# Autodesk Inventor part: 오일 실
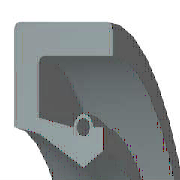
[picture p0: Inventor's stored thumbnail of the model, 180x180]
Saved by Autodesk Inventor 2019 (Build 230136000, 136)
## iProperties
IsCustomPart: 0
Created: 2016-05
Part Number: 오일 실
Material: 고무
Description: 오일-실
Document SubType Name: Modeling
Standard: KS B 2804
Designer: mduedu
Standards Organization: KS
Language: ko-KR
Size Designation: S - 17 30 8
Categories: <MemberInstance><Categories><Category DisplayName="샤프트 부품" InternalName="7f7aeb1f-a693-4053-b835-cee3144e0d98" Mnemonic="SHFT"><Category DisplayName="실링" Intern
Density: 0.93 g/cm^3
Appearance: 고무 - 검은색 - 버전 1.1
Author: mduedu
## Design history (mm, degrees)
revolve "본체" stored, may be unused: angle "d17" = 90 deg
revolve "스프링1" stored, may be unused: angle "d18" = 90 deg
body "Solid1"
sketch "스케치1"
  geometry: L1 (0, 15)-(8, 15); L2 (8, 15)-(8, 13.75); L3 (8, 13.75)-(1.75, 13.75); L4 (0, 15)-(0, 10.6); L5 (0, 10.6)-(1.75, 10.25); L6 (1.75, 10.25)-(4.9, 8.5); L7 (4.9, 8.5)-(0, 8.5); L8 (6.3, 9.375)-(6.3, 10.6); L9 (0, 0)-(9.586, 0) reference; L10 (4.9, 8.5)-(6.3, 9.375); L11 (0, 18)-(0, -3) reference; L12 (-1.917, 0)-(11.503, 0) reference; L13 (4.2, 10.6)-(1.75, 11.09); L14 (1.75, 11.09)-(1.75, 13.75); L15 (6.3, 10.6)-(5.6, 10.6); C1 r 0.455 at (4.9, 10.6); A1 r 0.7 centre (4.9, 10.6) between (5.6, 10.6) and (4.2, 10.6)
  constraints: 26 end point, 5 horizontal alignment, 4 perpendicular, 2 centre point, 2 collinear, 2 horizontal, 2 parallel, 2 point on circle, 2 point on line, 2 vertical alignment, 1 coincident
  dimensions: "d0" = 30 diameter of L1 L9 (= SD2); "d1" = 18.75 diameter of L8.start L9 (= ABDM); "d2" = 1.25 distance of L1.end L2.end (computed from SD); "d3" = 0.91 diameter of C1 (= SPDI); "d4" = 1.4 diameter of A1 (= SPDA); "d5" = 17 diameter of L6.end L9 (= NND); "d6" = 20.5 diameter of L5.end L9 (= TKDM); "d7" = 21.2 diameter of L4.end L9 (= HLDM); "d8" = 4.9 distance from line of C1.centre L4 (= SPDST); "d9" = 6.3 distance between parallel lines of L8 L4 (= SDI); "d10" = 8 distance between parallel lines of L2 L4 (= SWDT); "d12" = 1.75 distance between parallel lines of L14 L4 (= SD)
fillet "모깎기1" dims "d11" = 0.3 (= RR)
other parameters: "SD2" = 30 [user parameter; used in 1 equation term], "SWDT" = 8 [user parameter; used in 1 equation term], "RR" = 0.3 [user parameter; used in 1 equation term], "SD" = 1.75 [user parameter; used in 2 equation terms], "NND" = 17 [user parameter; used in 1 equation term], "SPDA" = 1.4 [user parameter; used in 1 equation term], "SPDI" = 0.91 [user parameter; used in 1 equation term], "TKDM" = 20.5 [user parameter; used in 1 equation term], "HLDM" = 21.2 [user parameter; used in 1 equation term], "ABDM" = 18.75 [user parameter; used in 1 equation term], "SDI" = 6.3 [user parameter; used in 1 equation term], "SPDST" = 4.9 [user parameter; used in 1 equation term], "d13" = 0, "d14" = 0, "d15" = 0, "LAB" = 0.35 [user parameter]
